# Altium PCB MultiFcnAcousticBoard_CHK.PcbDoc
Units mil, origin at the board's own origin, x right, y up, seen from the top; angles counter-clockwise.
Board outline 6000 x 4000 mil, 2 copper layers (Top Layer, Bottom Layer); 109 components, 99 nets, 325 pads, 43 vias.
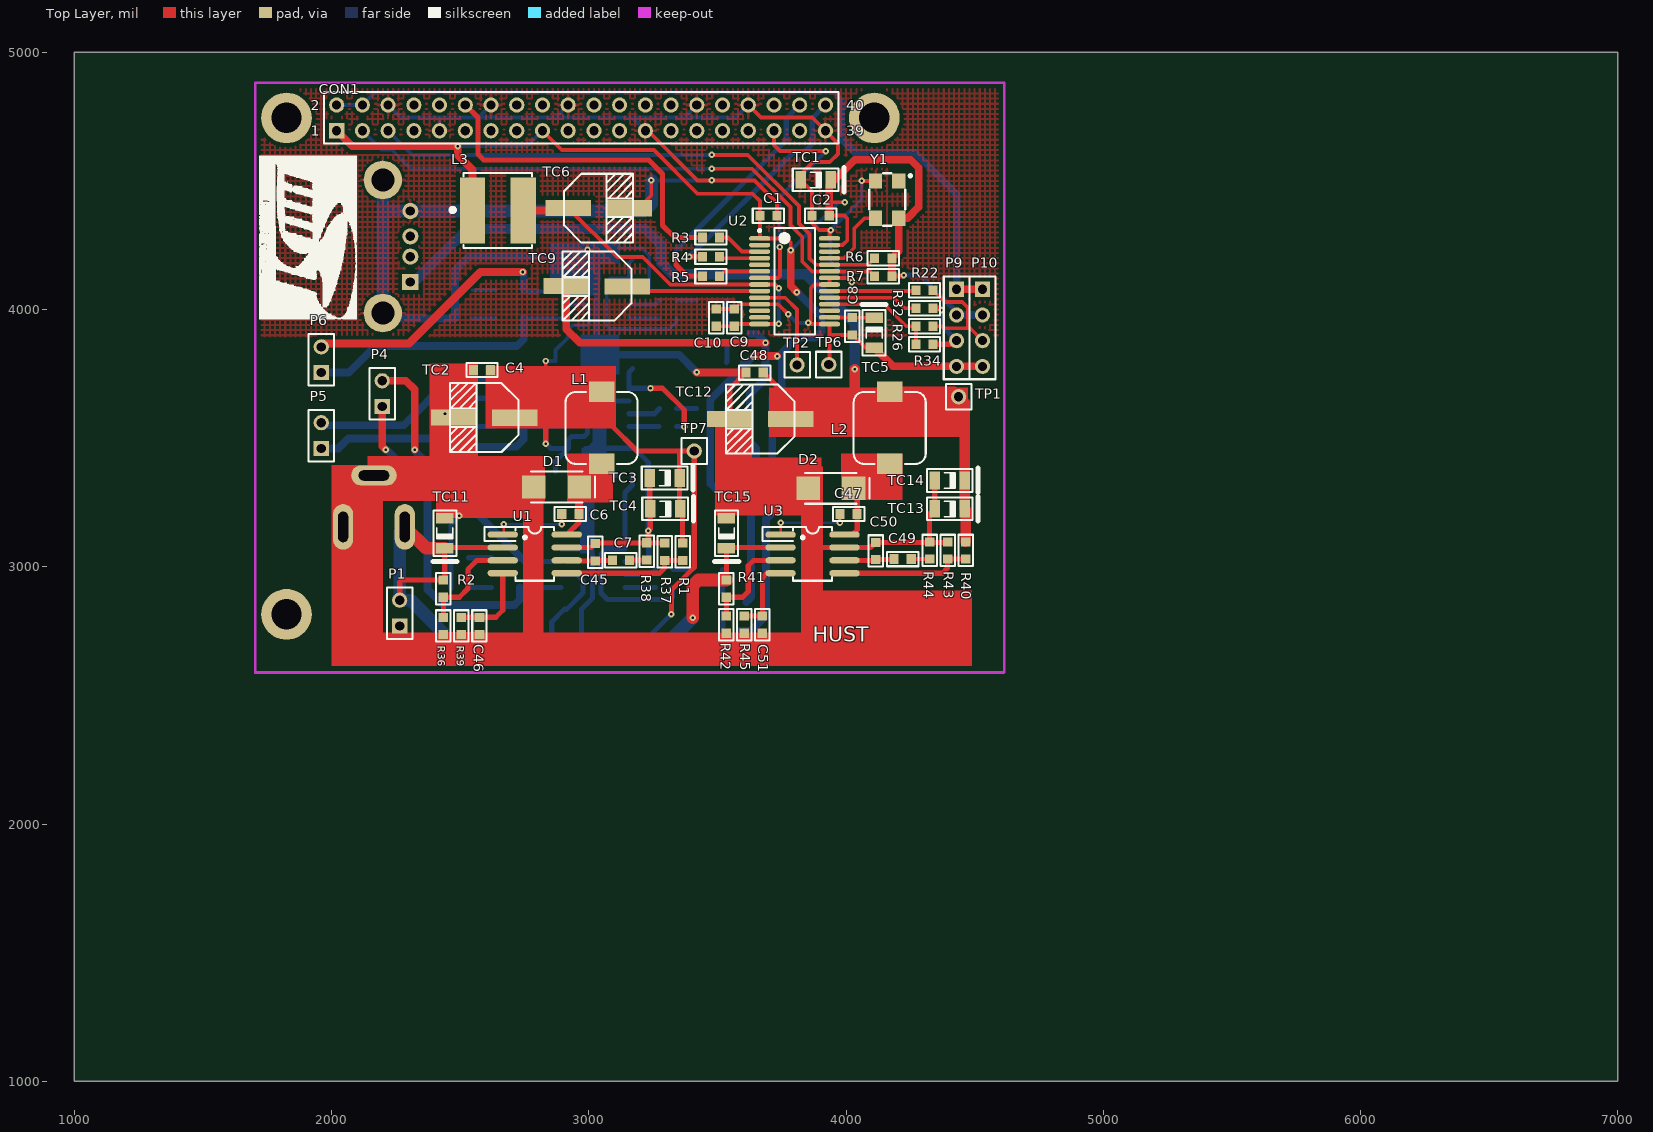
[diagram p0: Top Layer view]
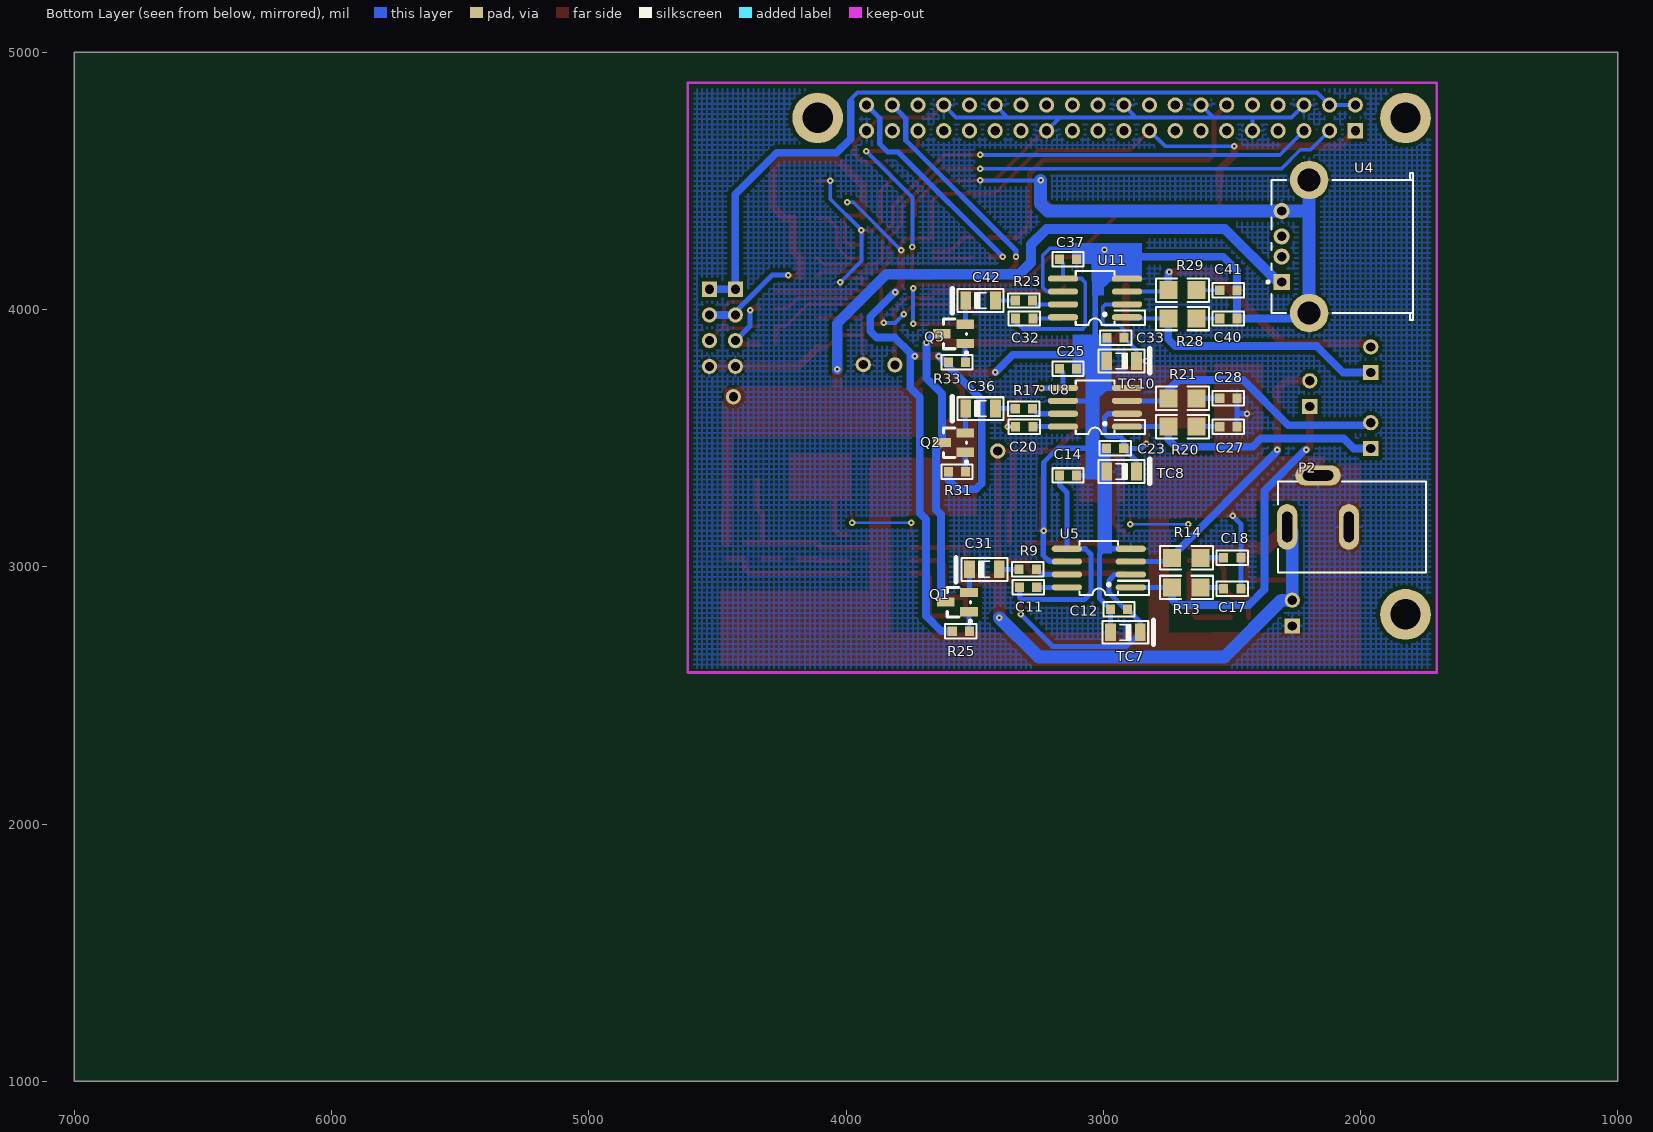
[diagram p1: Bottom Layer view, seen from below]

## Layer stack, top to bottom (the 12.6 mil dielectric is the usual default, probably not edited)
Top Solder: solder mask 0.4, Solder Resist, Dk 3.5
Top Layer: signal copper 1.4
Dielectric 1: dielectric 12.6, FR-4, Dk 4.8
Bottom Layer: signal copper 1.4
Bottom Solder: solder mask 0.4, Solder Resist, Dk 3.5

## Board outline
1000,1000 7000,1000 7000,5000 1000,5000

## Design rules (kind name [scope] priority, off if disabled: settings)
Clearance [All] p1: gap=15
PolygonConnect [All] p1: connectstyle=Relief reliefconductorwidth=10 reliefentries=4 polygonreliefangle="90 Angle" airgapwidth=10
RoutingVias [All] p1: holewidth=28 width=50 viastyle="Through Hole" minholewidth=5 minwidth=10 maxholewidth=50 maxwidth=100
SolderMaskExpansion [All] p1: expansion=4
Width [All] p1: maxlimit=100 minlimit=10 preferedwidth=30
30 further rules are at their usual default settings.

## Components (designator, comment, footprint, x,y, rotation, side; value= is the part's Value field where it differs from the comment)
C1 "0.1uF/0603" C0603 3698.46,4365 r180 top
C2 "0.1uF/0603" C0603 3901.54,4365 r0 top
C4 "0.1uF/0603" C0603 2585,3765 r0 top
C6 "0.1uF/0603" C0603 2928.46,3205 r0 top
C7 "180pF/0603" C0603 3125,3025 r180 top
C8 "0.1uF/0603" C0603 4025,3935 r90 top
C9 "0.1uF/0603" C0603 3565,3968.46 r270 top
C10 "0.1uF/0603" C0603 3495,3968.46 r270 top
C11 "10uF/0603" C0603 3292,2920 r180 bottom
C12 "0.1uF/0603" C0603 2938.54,2835 r180 bottom
C14 "10nF/0603" C0603 3137,3355 r0 bottom
C17 "0.1uF/0603" C0603 2498.54,2915 r0 bottom
C18 "0.1uF/0603" C0603 2498.54,3035 r0 bottom
C20 "10uF/0603" C0603 3307,3545 r180 bottom
C23 "0.1uF/0603" C0603 2953.54,3460 r180 bottom
C25 "10nF/0603" C0603 3137,3770 r0 bottom
C27 "0.1uF/0603" C0603 2513.54,3545 r0 bottom
C28 "0.1uF/0603" C0603 2513.54,3655 r0 bottom
C31 "1uF/1206" TAN_A 3462,2990 r0 bottom
C32 "10uF/0603" C0603 3307,3965 r180 bottom
C33 "0.1uF/0603" C0603 2952,3890 r180 bottom
C36 "1uF/1206" TAN_A 3477,3615 r0 bottom
C37 "10nF/0603" C0603 3137,4195 r0 bottom
C40 "0.1uF/0603" C0603 2513.54,3965 r0 bottom
C41 "0.1uF/0603" C0603 2513.54,4075 r0 bottom
C42 "1uF/1206" TAN_A 3477,4035 r0 bottom
C45 "10pF/0603" C0603 3025,3056.54 r270 top
C46 "0.015uF/0603" C0603 2575,2770 r90 top
C47 "0.1uF/0603" C0603 4010,3205 r0 top
C48 "0.1uF/0603" C0603 3645,3755 r0 top
C49 "180pF/0603" C0603 4220,3030 r180 top
C50 "10pF/0603" C0603 4115,3061.54 r270 top
C51 "0.015uF/0603" C0603 3675,2775 r90 top
CON1 "RPI_40PIN_CON" HDR2X20 2020,4695 r0 top
D1 "B320A-SMA" DIODE-SMA 2875,3310 r0 top
D2 "B320A-SMA" DIODE-SMA 3941.42,3305 r0 top
L1 "2.5uH/1264EY-100M=P3" L-SMD-7 3050,3540 r90 top
L2 "2.5uH/1264EY-100M=P3" L-SMD-7 4170,3540 r90 top
L3 "10uH/1264EY-100M=P3" INDUCTOR 2548.15,4385 r0 top
P1 "Header 2" HDR1X2 2265,2770 r90 top
P2 "Header 3" DC-005 2320,3155 r180 bottom
P4 "Header 2" HDR1X2 2197,3623 r90 top
P5 "Header 2" HDR1X2 1960,3460 r90 top
P6 "Header 2" HDR1X2 1960,3755 r90 top
P9 "Header 4" HDR1X4 4430,4079 r270 top
P10 "Header 4" HDR1X4 4531,4079 r270 top
Q1 "MMBT3904" SOT-23 3566.72,2862.5 r90 bottom
Q2 "MMBT3904" SOT-23 3581.72,3482.5 r90 bottom
Q3 "MMBT3904" SOT-23 3582,3905 r90 bottom
R1 "10.2K/0603" R0603 3365,3058.46 r90 top
R2 "150K/0603" R0603 2435,2915 r270 top
R3 "27 ohm/0603" R0603 3475,4280 r180 top
R4 "1K/0603" R0603 3475,4205 r180 top
R5 "27 ohm/0603" R0603 3475,4130 r180 top
R6 "1K/0603" R0603 4145,4200 r0 top
R7 "1K/0603" R0603 4145,4130 r0 top
R9 "10k" R0603 3293.54,2990 r180 bottom
R13 "4.7R" 0805 2622,2920 r0 bottom
R14 "4.7R" 0805 2622,3035 r0 bottom
R17 "10k" R0603 3308.54,3615 r180 bottom
R20 "4.7R" 0805 2637,3545 r0 bottom
R21 "4.7R" 0805 2637,3655 r0 bottom
R22 "0" R0603 4305,4075 r0 top
R23 "10k" R0603 3308.54,4035 r180 bottom
R25 "20k" R0603 3553.54,2750 r0 bottom
R26 "0" R0603 4305,3935 r0 top
R28 "4.7R" 0805 2637,3965 r0 bottom
R29 "4.7R" 0805 2637,4075 r0 bottom
R31 "20k" R0603 3568.54,3370 r0 bottom
R32 "0" R0603 4305,4005 r0 top
R33 "20k" R0603 3568.54,3795 r0 bottom
R34 "0" R0603 4305,3865 r0 top
R36 "48.7K/0603" R0603 2435,2770 r90 top
R37 "4.75K/0603" R0603 3295,3058.46 r270 top
R38 "75K/0603" R0603 3225,3060 r270 top
R39 "1M/0603" R0603 2505,2770 r90 top
R40 "10.2K/0603" R0603 4465,3063.46 r90 top
R41 "150K/0603" R0603 3535,2915 r270 top
R42 "48.7K/0603" R0603 3535,2775 r90 top
R43 "4.75K/0603" R0603 4395,3063.46 r270 top
R44 "75K/0603" R0603 4325,3063.46 r270 top
R45 "1M/0603" R0603 3605,2775 r90 top
TC1 "10uF/TAN/1206" TAN_A 3882,4504 r0 top
TC2 "1000uF" TAN_CAP 2712,3579 r180 top
TC3 "47uF" TAN_A 3295,3345 r0 top
TC4 "47uF" TAN_A 3296.93,3225 r0 top
TC5 "10uF/TAN/1206" TAN_A 4110,3910 r90 top
TC6 "10uF/TAN/1206" TAN_CAP 2920,4395 r0 top
TC7 "10uF" TAN_A 2913.93,2745 r180 bottom
TC8 "10uF" TAN_A 2928.93,3370 r180 bottom
TC9 "330uF" TAN_CAP 3150,4090 r180 top
TC10 "10uF" TAN_A 2928.93,3800 r180 bottom
TC11 "10uF" TAN_A 2440,3130 r270 top
TC12 "1000uF" TAN_CAP 3785,3574 r180 top
TC13 "47uF" TAN_A 4403.07,3225 r0 top
TC14 "47uF" TAN_A 4403.07,3335 r0 top
TC15 "10uF" TAN_A 3535,3130 r270 top
TP1 "VCC_5" TP 4440,3660 r0 top
TP2 "RPOUT" TP 3811.98,3784.16 r0 top
TP6 "GND" TP 3935,3785 r0 top
TP7 "VCC_12" TP 3411.98,3449.16 r0 top
U1 "TPS54432" SOIC-8 2790,3050 r0 top
U2 "WM8731SEDS/RV" SSOP-28 3800,4110 r0 top
U3 "TPS54432" SOIC-8 3870,3050 r0 top
U4 "USB" USB_A1 1795,4245 r180 bottom
U5 "TDA2822" SOIC-8 3017,2995 r0 bottom
U8 "TDA2822" SOIC-8 3032,3620 r0 bottom
U11 "TDA2822" SOIC-8 3032,4045 r0 bottom
Y1 "XATLS" 5032 4165,4430 r90 top

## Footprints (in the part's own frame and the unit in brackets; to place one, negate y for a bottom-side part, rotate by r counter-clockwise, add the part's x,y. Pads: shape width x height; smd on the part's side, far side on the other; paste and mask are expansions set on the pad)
0805 [mil]
  rect 70x70 smd: 1(0,0) 2(110,0)
  silkscreen extent -48,-45 158,46
5032 [mm]
  rect 1.5x1.3 smd: 1(1.778,-1.016) 2(1.778,1.27) 3(-1.905,1.27) 4(-1.905,-1.016)
  silkscreen extent -2.67,-2.29 2.54,1.91
C0603 [mm]
  rect 0.9x0.95 smd: 1(0.85,0) 2(-0.85,0)
  silkscreen extent -1.55,-0.71 1.55,0.71, body extent -0.85,-0.45 0.85,0.45, height 0.45
DC-005 [mm] "DC母座5.5mm"
  oval 2x4.5 hole 1 slot 3 at 90 deg: 1(0.889,0) 2(6.985,0)
  oval 4.5x2 hole 1 slot 3 at 0 deg: 3(3.937,5.08)
  silkscreen extent 0,-4.5 14.6,4.5, body extent 0,-4.45 14.6,4.44, height 11
DIODE-SMA [mm] "贴片二极管"
  rect 2.3x2.3 smd: 1(-2.25,0) 2(2.25,0)
  silkscreen extent -2.54,-1.52 3.81,1.52, body extent -2.92,-1.4 2.92,1.4, height 3
HDR1X2 [mm] "Connector; Header; 2 Position"
  rect 1.5x1.5 hole 0.9: 1(0,0)
  round 1.5 hole 0.9: 2(2.54,0)
  silkscreen extent -1.27,-1.27 3.81,1.27
HDR1X4 [mm] "Connector; Header; 4 Position"
  rect 1.5x1.5 hole 0.9: 1(0,0)
  round 1.5 hole 0.9: 2(2.54,0) 3(5.08,0) 4(7.62,0)
  silkscreen extent -1.27,-1.27 8.89,1.27
HDR2X20 [mm] "Connector; Header; 20x2 Position"
  rect 1.5x1.5 hole 0.9: 1(0,0)
  round 1.5 hole 0.9: 2(0,2.54) 3(2.54,0) 4(2.54,2.54) 5(5.08,0) 6(5.08,2.54) 7(7.62,0) 8(7.62,2.54) 9(10.16,0) 10(10.16,2.54) 11(12.7,0) 12(12.7,2.54) 13(15.24,0) 14(15.24,2.54) 15(17.78,0) 16(17.78,2.54) 17(20.32,0) 18(20.32,2.54) 19(22.86,0) 20(22.86,2.54) 21(25.4,0) 22(25.4,2.54) 23(27.94,0) 24(27.94,2.54) 25(30.48,0) 26(30.48,2.54) 27(33.02,0) 28(33.02,2.54) 29(35.56,0) 30(35.56,2.54) 31(38.1,0) 32(38.1,2.54) 33(40.64,0) 34(40.64,2.54) 35(43.18,0) 36(43.18,2.54) 37(45.72,0) 38(45.72,2.54) 39(48.26,0) 40(48.26,2.54)
  silkscreen extent -1.27,-1.27 49.53,3.81
INDUCTOR [mm]
  rect 2.5x6.5 smd: 1(0,0) 2(5,0)
  silkscreen extent -2.11,-3.7 5.88,3.7
L-SMD-7 [mm] "贴片电感7*7"
  rect 2x2.5 smd: 1(-3.556,0) 2(3.556,0)
  silkscreen extent -3.56,-3.56 3.56,3.56, body extent -3.56,-3.56 3.56,3.56, height 4
R0603 [mm]
  rect 0.9x0.95 smd: 1(0.85,0) 2(-0.85,0)
  silkscreen extent -1.55,-0.71 1.55,0.71, body extent -0.85,-0.45 0.85,0.45, height 0.45
SOIC-8 [mil] "SOIC, 8-Leads, Body 5.0x4.0mm (max), Pitch 1.27mm, IPC Medium Density"
  oval 118.11x24 smd: 1(-124.32,75) 2(-124.32,25) 3(-124.32,-25) 4(-124.32,-75) 5(124.32,-75) 6(124.32,-25) 7(124.32,25) 8(124.32,75)
  silkscreen extent -195,-104 75,104, body extent -75,-99 75,101, height 69
SOT-23 [mil]
  rect 36x68.9 smd: 1(-37.5,-45.28) 2(37.5,-45.28) 3(0.5,45.28)
  silkscreen extent -79,-55 58,40, body extent -58,-35 60,20, height 47
SSOP-28 [mm] "FT232"
  oval 2.1x0.45 smd: 1(-3.45,4.225) 2(-3.45,3.575) 3(-3.45,2.925) 4(-3.45,2.275) 5(-3.45,1.625) 6(-3.45,0.975) 7(-3.45,0.325) 8(-3.45,-0.325) 9(-3.45,-0.975) 10(-3.45,-1.625) 11(-3.45,-2.275) 12(-3.45,-2.925) 13(-3.45,-3.575) 14(-3.45,-4.225) 15(3.45,-4.225) 16(3.45,-3.575) 17(3.45,-2.925) 18(3.45,-2.275) 19(3.45,-1.625) 20(3.45,-0.975) 21(3.45,-0.325) 22(3.45,0.325) 23(3.45,0.975) 24(3.45,1.625) 25(3.45,2.275) 26(3.45,2.925) 27(3.45,3.575) 28(3.45,4.225)
  silkscreen extent -3.57,-5.25 2,5.25, body extent -2.8,-5.25 2.8,5.25, height 2
TAN_A [mm]
  rect 1.05x1.75 smd: 1(1.475,0) 2(-1.475,0)
  silkscreen extent -2.26,-1.17 2.79,1.22, body extent -1.6,-0.85 1.6,0.85, height 0.55
TAN_CAP [mm]
  rect 4.5x1.6 smd: 1(0,0) 2(6.02,-0.025)
  silkscreen extent -0.4,-3.43 6.4,3.37
TP [mm]
  round 1.5 hole 0.9: 1(-0.05,0.021)
  silkscreen extent -1.32,-1.25 1.22,1.29
USB_A1 [mm]
  rect 1.6x1.6 hole 0.92: 1(-12.99,-3.5)
  round 1.6 hole 0.92: 2(-12.99,-1) 3(-12.99,1) 4(-12.99,3.5)
  round 3.8 hole 2.3: 5(-10.28,6.57) 6(-10.28,-6.57)
  silkscreen extent -14.47,-7.25 0,7.25

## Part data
C1 C2 C4 C6 C7 C8 C9 C10 C11 C12 C14 C17 C18 C20 C23 C25 C27 C28 C31 C32 C33 C36 C37 C40 C41 C42 C45 C46 C47 C48 C49 C50 C51: library part C
D1 D2: library part "Diode 1N4003", "1 Amp General Purpose Rectifier"
L1 L2 L3: library part L
P1 P4 P5 P6: "Header, 2-Pin"
P2: "Header, 3-Pin"
P9 P10: "Header, 4-Pin"
Q1 Q2 Q3: "NPN Transistor"
R1 R2 R3 R4 R5 R6 R7 R9 R13 R14 R17 R20 R21 R22 R23 R25 R26 R28 R29 R31 R32 R33 R34 R36 R37 R38 R39 R40 R41 R42 R43 R44 R45: library part RES
TC1 TC2 TC3 TC4 TC5 TC6 TC7 TC8 TC9 TC10 TC11 TC12 TC13 TC14 TC15: library part TAN_C
TP1 TP2 TP6 TP7: library part Testpoint
U1 U3: library part TPS54332
U2: library part XWM8731EDS
Y1: "贴片有源晶振"

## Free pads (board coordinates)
  round 196.85 hole 118.11: 0(4110,4745) 1(1825,4745) 2(1825,2815)

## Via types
v1: diameter 25, hole 10, Top Layer to Bottom Layer, 43 vias

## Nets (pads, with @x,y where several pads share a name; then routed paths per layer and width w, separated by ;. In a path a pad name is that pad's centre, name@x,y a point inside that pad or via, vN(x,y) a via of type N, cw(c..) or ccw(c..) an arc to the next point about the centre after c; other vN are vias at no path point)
3V3: C1.1 C2.1 CON1.1 CON1.17 L3.1 P9.2 P10.2 R6.1 R7.1 R25.1 R31.1 R33.1 TC1.1 U2.1 U2.27 Y1.4 | length 7004.8
  Top Layer w15: L3.1 L3.1@2548.15,4492 ; CON1.17 2895,4620 3253,4620 3423,4450 3637,4450 3665,4422 C1.1 3665,4277.17 U2.1 3769.66,4276.34 3785,4261 v1(3785,4230) ; C2.1 3994,4365 4005,4354 4005,4269 3986.75,4250.75 U2.27 ; 3935,4415 3937,4417 v1(3995,4417)
  Top Layer w20: R7.1 4221,4130 v1(4225,4134)
  Top Layer w30: CON1.1 2080,4635 v1(2491,4635) 2491,4600 2548.15,4542.85 L3.1@2548.15,4492 ; v1(3639,3819) v1(3732,3819) ; v1(3785,4230) 3785,4092 v1(3809,4068) ; C2.1 3935,4415 3935,4483 4034,4582 4252,4582 4283,4551 4283,4399 4239,4355 Y1.4 4205,4226.54 R6.1 R7.1
  Bottom Layer w15: v1(2491,4635) 2760,4635 CON1.17 ; v1(3785,4230) 3972,4417 v1(3995,4417)
  Bottom Layer w20: v1(4225,4134) 4287,4134 4430,3991 P9.2
  Bottom Layer w30: R25.1 3630,2750 3689,2809 3689,3185 3713,3209 3713,3659 3750,3696 3750,3831 ; R31.1 3602,3339 3564,3301 3495,3301 3472,3324 3472,3649 3602,3779 R33.1 3615,3795 v1(3639,3819) ; v1(3732,3819) 3738,3819 3750,3831 ; v1(3809,4068) 3809,4069 3906,3972 3906,3916 3881,3891 3810,3891 3750,3831 ; P9.2 P10.2
3V_L: 
3V_R: 
5V: CON1.2 CON1.4 P9.1 P10.1 | length 3255
  Top Layer w30: P9.1 P10.1
  Bottom Layer w15: CON1.2 CON1.4 2169,4844 3955,4844 3982,4817 3982,4808
  Bottom Layer w30: 3982,4808 3982,4664 4037,4609 4269,4609 4430,4448 P9.1 P10.1
5V_L: 
5V_R: 
ACD_MISO: CON1.38 R5.1 | length 941.6
  Top Layer w20: v1(3339,4206) 3339,4173 3382,4130 R5.1
  Bottom Layer w20: v1(3339,4206) 3339,4229 3768,4658 3768,4743 CON1.38
ACD_MOSI: CON1.40 R4.1 | length 884.5
  Top Layer w20: v1(3390,4205) R4.1
  Bottom Layer w20: v1(3390,4205) 3797.5,4612.5 3837.5,4612.5 3869,4644 3869,4744 CON1.40
ACD_SCK: CON1.12 R3.1 | length 1335.2
  Top Layer w20: CON1.12 2569,4746 2569,4604 2592,4581 3233,4581 3287,4527 3287,4327 3334,4280 R3.1
ADCLRC: CON1.35 U2.7 | length 911
  Top Layer w15: U2.7 3735.8,4122.8 3743.8,4130.8 3743.8,4241.2 v1(3742,4243) ; CON1.35 3720,4639 3743,4616 v1(3922,4616)
  Bottom Layer w15: v1(3742,4243) 3742,4436 v1(3922,4616)
AMP1: C31.2 R9.2 | length 76.9
  Bottom Layer w20: R9.2 C31.2
AMP2: C36.2 R17.2 | length 76.9
  Bottom Layer w20: R17.2 C36.2
AMP3: C42.2 R23.2 | length 76.9
  Bottom Layer w15: R23.2 C42.2
BAT_IN: P1.2 P2.1 R2.2 R41.2 TC11.1 TC15.1 U1.2 U3.2 | length 2973.5
  Top Layer w20: P1.2 2265,2941 2272.46,2948.46 R2.2 2440,2953.46 TC11.1 2443.07,3075 U1.2 ; R41.2 TC15.1 3538.07,3075 U3.2
  Top Layer w50: P2.1 2368.07,3071.93 TC11.1 ; v1(3404,2802) 3404,2927 3425.46,2948.46 R41.2
  Bottom Layer w50: P2.1 2265,3135 P1.2 2308,2870 2529,2649 3251,2649 v1(3404,2802)
GND: C1.2 C2.2 C4.2 C8.2 C9.2 C10.2 C12.2 C14.2 C17.2 C18.2 C23.2 C25.2 C27.2 C28.2 C33.2 C37.2 C40.2 C41.2 C45.2 C46.2 C48.2 C50.2 C51.2 CON1.6 CON1.9 CON1.14 CON1.20 CON1.25 CON1.30 CON1.34 CON1.39 D1.1 D2.1 P1.1 P2.2 P2.3 P9.4 P10.4 R36.2 R37.2 R38.2 R39.2 R42.2 R43.2 R44.2 R45.2 TC1.2 TC2.2 TC3.2 TC4.2 TC5.2 TC6.2 TC7.2 TC8.2 TC10.2 TC11.2 TC12.2 TC13.2 TC14.2 TC15.2 TP6.1 U1.7 U2.11 U2.15 U2.21 U2.22 U2.28 U3.7 U4.4 U4.5 U4.6 U5.4 U5.6 U8.4 U8.6 U11.4 U11.6 Y1.2 | length 14433.1
  Top Layer w15: TC6.2 3193,4394 3243,4444 v1(3243,4503) ; CON1.25 3230,4695 3423,4502 v1(3478,4502) 3644,4502 3731.93,4414.07 C1.2 ; C10.2 C9.2 3583.5,4020.43 U2.11 3736.57,4020.43 v1(3776,3981) ; CON1.34 3669,4746 3869,4746 CON1.39 3969,4646 3969,4605 3937,4573 3871,4573 3823.93,4525.93 TC1.2 3868.07,4459.86 C2.2 3868.07,4336.93 3896,4309 v1(3940,4309) 3935.83,4304.83 U2.28 ; TP6.1 3935.83,3788.64 3935.83,3901.54 ; v1(4022,4106) 4005.2,4122.8 U2.22 U2.21 3877.2,4097.2 3863,4083 3863,3958 v1(3853,3948) 3857.34,3943.66 U2.15 3935.83,3901.54 ; v1(4061,4500) Y1.2 ; TC5.2 4074.61,3851.93 C8.2 3935.83,3901.54
  Top Layer w20: 2265,2699 P1.1 ; R36.2 R39.2 C46.2 ; U1.7 3010,3075 C45.2 3026.93,3091.93 R37.2 ; R38.2 3231,3099.46 v1(3231,3140) 3238.86,3147.86 TC4.2 3236.93,3226.93 TC3.2 ; TC12.2 3548,3691.46 C48.2 ; 3865,3085 3875,3085 3885,3075 U3.7 4095,3075 C50.2 4393.07,3095 R43.2 ; R44.2 4325,3205 TC13.2 TC14.2
  Top Layer w30: v1(3419,3756) 3420,3755 C48.2 ; TC5.2 4110.07,3851.93 4183,3779 P9.4 P10.4
  Bottom Layer w15: CON1.6 2268,4747 2426,4747 ; CON1.9 2420,4741 2426,4747 ; CON1.14 2572,4747 ; CON1.20 2872,4747 ; C37.2 3103.54,4238 3207,4238 3235,4210 3235,4086 3219,4070 U11.6 ; CON1.25 3168,4747 ; v1@3244,4502 v1(3478,4502) ; CON1.30 3372,4747 ; CON1.34 3572,4747 3372,4747 ; v1(3776,3981) 3809,3948 v1(3853,3948) ; v1(4022,4106) 3940,4188 v1(3940,4309) 4061,4430 v1(4061,4500) ; 2426,4747 2572,4747 ; 2572,4747 2872,4747 ; 2872,4747 3168,4747 ; 3168,4747 3372,4747
  Bottom Layer w20: v1(2441,3595) 2480.07,3595 ; C17.2 C18.2 2465.07,3166.07 v1(2497,3198) ; C27.2 2480.07,3595 ; C28.2 2480.07,3595 ; U5.4 2994,3070 3015,3049 3015,2878 C12.2 TC7.2 ; U8.4 2991,3695 3041,3645 ; TC8.2 C23.2 3002,3460 3041,3499 3041,3645 ; TC10.2 2985.46,3801.54 C33.2 3031,3890 3031,4065 2976,4120 U11.4 2982.68,4195 C37.2 ; v1(2995,4232) 3041,4232 ; 3035,3461 3176,3461 3231,3406 v1(3231,3140) 3233,3138 3233,3044 3209,3020 U5.6 ; 3038,3355 C14.2 ; U8.6 3041,3645
  Bottom Layer w30: U4.6 2221.06,3965 C40.2 C41.2 2480.07,4152.07 2533,4205 2909,4205 ; TC10.2 3017,3770 C25.2 ; 3092,3824 3351,3824 v1(3419,3756)
  Bottom Layer w50: U4.6 2199.72,4366 ; U4.5 2199.72,4366 ; v1@3244,4502 3244,4411 3215.8,4382.8 U4.4 2216.52,4382.8 2199.72,4366
I2C_SCL: CON1.5 R6.2 U2.24 | length 2213
  Top Layer w15: v1(3478,4601) 3618,4601 3817,4402 3817,4335 3858,4294 3858,4199 3883.02,4173.98 U2.24 4085.51,4173.98 R6.2
  Bottom Layer w15: CON1.5 2314,4601 v1(3478,4601)
I2C_SDA: CON1.3 R7.2 U2.23 | length 2322.2
  Top Layer w15: v1(3477.5,4547.5) 3634.5,4547.5 3784,4398 3784,4328 3830,4282 3830,4187 3868.61,4148.39 U2.23 4093.15,4148.39 R7.2
  Bottom Layer w15: CON1.3 2194,4621 2234,4621 2307.5,4547.5 v1(3477.5,4547.5)
L: 
LCHAL: 
LCHL: P10.3 R22.1 R26.1 | length 459.4
  Top Layer w15: R26.1 4373,3935 4381,3927 4474,3927 ; R22.1 4384.46,4029 4452,4029 4474,4007 4474,3927 ; P10.3 4483,3927 4474,3927
LLIN: R22.2 U2.20 | length 337.1
  Top Layer w15: U2.20 4268.15,4071.61 R22.2
LPOUT: TC9.1 U2.9 | length 521.8
  Top Layer w15: TC9.1 3168.39,4071.61 U2.9
MICBIAS1: 
MICBIAS2: 
MICIN: R26.2 R34.2 U2.18 | length 441.1
  Top Layer w15: U2.18 4148.57,4020.43 4234,3935 R26.2 R34.2
NetC6_1: C6.1 D1.2 L1.1 U1.8 | length 205.4
  Top Layer w20: U1.8 2961.93,3172.61 C6.1
  Top Layer w30: C6.1 2961.93,3308.35 D1.2
NetC6_2: C6.2 U1.1 | length 306.8
  Top Layer w10: U1.1 2670,3129.32 v1(2670,3165) ; v1(2895,3165) C6.2
  Bottom Layer w10: v1(2670,3165) v1(2895,3165)
NetC7_1: C7.1 C45.1 U1.6 | length 178.8
  Top Layer w20: U1.6 2916.24,3023.07 C45.1 3026.93,3025 C7.1
NetC7_2: C7.2 R38.1 | length 67.2
  Top Layer w20: C7.2 3160,3026.54 R38.1
NetC8_1: C8.1 TC5.1 U2.16 | length 174.7
  Top Layer w15: U2.16 4024.21,3969.25 C8.1 4025.39,3968.07 TC5.1
NetC9_1: C9.1 C10.1 L3.2 TC6.1 U2.8 U2.14 | length 1514.1
  Top Layer w15: TC6.1@2875,4385 2910,4385 TC6.1 3111,4204 3210,4204 3316.8,4097.2 U2.8 3724.8,4097.2 v1(3739,4083) ; C10.1 C9.1 3573.66,3943.66 U2.14 3664.51,3944 v1(3739,3944)
  Top Layer w30: L3.2 TC6.1@2875,4385
  Bottom Layer w15: v1(3739,3944) v1(3739,4083)
NetC11_1: C11.1 U5.8 | length 117.2
  Bottom Layer w20: U5.8 C11.1
NetC11_2: C11.2 C14.1 U5.5 | length 879.4
  Bottom Layer w20: C14.1 3170.46,3317.46 3141.32,3288.32 U5.5 3070,3070 3048,3048 3048,2898 3073,2873 3317,2873 3325.46,2881.46 C11.2
NetC17_1: C17.1 R13.1 | length 92.1
  Bottom Layer w20: C17.1 2537,2920 R13.1
NetC18_1: C18.1 R14.1 | length 90
  Bottom Layer w20: C18.1 R14.1
NetC20_1: C20.1 U8.8 | length 117.2
  Bottom Layer w20: U8.8 C20.1
NetC20_2: C20.2 C25.1 U8.5 | length 426.3
  Top Layer w20: v1(3240,3694) 3287,3694 3371,3610 v1(3371,3545)
  Bottom Layer w20: C25.1 3156.32,3755.85 U8.5 3157.32,3694 v1(3240,3694) ; C20.2 v1(3371,3545)
NetC21_1: 
NetC22_1: 
NetC24_1: 
NetC27_1: C27.1 R20.1 | length 90
  Bottom Layer w20: C27.1 R20.1
NetC28_1: C28.1 R21.1 | length 90
  Bottom Layer w20: C28.1 R21.1
NetC29_1: 
NetC30_2: 
NetC31_1: C31.1 Q1.2 | length 90.6
  Bottom Layer w20: C31.1 3520.07,2901.38 Q1.2
NetC32_1: C32.1 U11.8 | length 119.3
  Bottom Layer w15: U11.8 3161.32,3965 C32.1
NetC32_2: C32.2 C37.1 U11.5 | length 643.3
  Bottom Layer w15: C37.1 3156.32,4180.85 U11.5 3085,4120 3070,4105 3070,3935 3081,3924 3313,3924 3340.46,3951.46 C32.2
NetC34_1: 
NetC35_1: 
NetC36_1: C36.1 Q2.2 | length 95.6
  Bottom Layer w20: C36.1 3535.07,3521.38 Q2.2
NetC38_1: 
NetC40_1: C40.1 R28.1 | length 90
  Bottom Layer w15: C40.1 R28.1
NetC41_1: C41.1 R29.1 | length 90
  Bottom Layer w15: C41.1 R29.1
NetC42_1: C42.1 Q3.2 | length 93.2
  Bottom Layer w20: C42.1 3535.07,3944.15 Q3.2
NetC43_1: 
NetC44_2: 
NetC46_1: C46.1 R39.1 U1.4 | length 316.3
  Top Layer w20: R39.1 C46.1 2638.46,2803.46 2665.68,2830.68 U1.4
NetC47_1: C47.1 D2.2 L2.1 U3.8 | length 223.9
  Top Layer w20: U3.8 4025,3125 4043.46,3143.46 C47.1 4043.46,3291.54 D2.2
NetC47_2: C47.2 U3.1 | length 310.4
  Top Layer w10: U3.1 3745.68,3170.68 v1(3746.54,3171.54) ; v1(3976.54,3171.54) C47.2
  Bottom Layer w10: v1(3746.54,3171.54) v1(3976.54,3171.54)
NetC49_1: C49.1 C50.1 U3.6 | length 194.3
  Top Layer w10: C50.1@4111.93,3025 C50.1
  Top Layer w20: U3.6 C50.1@4111.93,3025 ; C50.1 4184.61,3028.07 C49.1
NetC49_2: C49.2 R44.1 | length 71.5
  Top Layer w15: C49.2 R44.1
NetC51_1: C51.1 R45.1 U3.4 | length 297.3
  Top Layer w20: R45.1 C51.1 3675,2958 3692,2975 U3.4
NetP11_1: 
NetP12_1: 
NetP12_2: 
NetQ1_1: Q1.1 R25.2 | length 75.6
  Bottom Layer w20: R25.2 3521.45,2751.38 Q1.1
NetQ1_3: Q1.3 Q2.3 Q3.3 TC9.2 | length 2095.1
  Top Layer w30: TC9.2 2913,3924 2966,3871 v1(3687,3871)
  Bottom Layer w30: Q1.3 3631,2882 3631,3203 3650,3222 3650,3460 Q2.3 3627,3673 3687,3733 v1(3687,3871) 3652.5,3905.5 Q3.3
NetQ2_1: Q2.1 R31.2 | length 75.6
  Bottom Layer w20: R31.2 3536.45,3371.38 Q2.1
NetQ3_1: Q3.1 R33.2 | length 73.2
  Bottom Layer w20: R33.2 3536.72,3796.65 Q3.1
NetR1_2: R1.2 R37.1 U1.5 | length 489
  Top Layer w20: U1.5 3275,2975 3295,2995 R37.1 R1.2
NetR2_1: R2.1 R36.1 U1.3 | length 412.1
  Top Layer w20: R36.1 R2.1 2496.54,2881.54 2530,2915 2530,2990 2565,3025 U1.3
NetR3_2: R3.2 U2.3 | length 178.4
  Top Layer w15: R3.2 3541,4280 3595.84,4225.16 U2.3
NetR4_2: R4.2 U2.4 | length 158
  Top Layer w15: R4.2 3513.9,4199.57 U2.4
NetR5_2: R5.2 U2.6 | length 163.3
  Top Layer w15: R5.2 3526.85,4148.39 U2.6
NetR9_1: R9.1 U5.7 | length 127
  Bottom Layer w20: U5.7 3240.07,2970 R9.1
NetR10_1: 
NetR12_1: 
NetR17_1: R17.1 U8.7 | length 127
  Bottom Layer w20: U8.7 3255.07,3595 R17.1
NetR18_1: 
NetR23_1: R23.1 U11.7 | length 125
  Bottom Layer w15: U11.7 3260.07,4020 R23.1
NetR27_1: 
NetR40_2: R40.2 R43.1 U3.5 | length 514
  Top Layer w20: U3.5 4375,2975 4395,2995 R43.1 R40.2
NetR41_1: R41.1 R42.1 U3.3 | length 401.8
  Top Layer w20: R42.1 R41.1 3597.54,2881.54 3620,2904 3620,3004 3641,3025 U3.3
NetU2_25: U2.25 Y1.3 | length 287.5
  Top Layer w15: U2.25 3991.57,4199.57 4032,4240 4032,4315 4072,4355 Y1.3
R: 
RCHAL: 
RCHL: P9.3 R32.1 R34.1 | length 267.5
  Top Layer w20: R34.1 4416,3865 P9.3 ; R32.1 v1@4366,4005
  Bottom Layer w20: v1(4373,3998) 4373,3936 P9.3
REF_L: 
REF_R: 
RLIN: R32.2 U2.19 | length 352.7
  Top Layer w15: U2.19 4185.98,4046.02 4227,4005 R32.2
RPOUT: TP2.1 U2.10 | length 379.9
  Top Layer w15: U2.10 3763.98,4046.02 3810,4000 TP2.1
SPL1_L: P4.1 R13.2 U5.1 | length 1387.3
  Top Layer w30: P4.1 2197,3469 v1(2211,3455)
  Bottom Layer w20: R13.2 U5.1
  Bottom Layer w30: v1(2211,3455) 2214,3455 2373,3296 2373,2912 2434,2851 2711,2851 2732,2872 R13.2
SPL1_R: P4.2 R14.2 U5.3 | length 1130.4
  Top Layer w30: P4.2 2289,3723 2323,3689 v1(2323,3455)
  Bottom Layer w20: R14.2 2747,3020 U5.3
  Bottom Layer w30: v1(2323,3455) 2323,3450 2732,3041 R14.2
SPL2_L: P5.1 R20.2 U8.1 | length 1038.1
  Bottom Layer w20: R20.2 U8.1
  Bottom Layer w30: P5.1 2027,3460 2066,3499 2387,3499 2419,3467 2718,3467 2747,3496 R20.2
SPL2_R: P5.2 R21.2 U8.3 | length 1076.4
  Bottom Layer w20: R21.2 2757,3645 U8.3
  Bottom Layer w30: P5.2 1970,3550 2280,3550 2456,3726 2707,3726 2747,3686 R21.2
SPL3_L: P6.1 R28.2 U11.1 | length 1083.6
  Bottom Layer w15: R28.2 2902.68,3965 U11.1
  Bottom Layer w30: P6.1 2067,3755 2170,3858 2720,3858 2747,3885 R28.2
SPL3_R: P6.2 R29.2 U11.3 | length 1139.5
  Top Layer w30: P6.2 1973,3868 2301,3868 2579,4146 v1(2744,4146)
  Bottom Layer w15: R29.2 2752,4070 U11.3
  Bottom Layer w30: v1(2744,4146) 2747,4143 R29.2
VCC_5V: C48.1 L2.2 R40.1 TC12.1 TC13.1 TC14.1 TP1.1 U4.1 | length 3869
  Top Layer w20: C48.1 3785,3648.46 TC12.1
  Top Layer w40: TC12.1 4129,3574 4170,3615 L2.2 4418.86,3680 TP1.1 4461.14,3637.72 TC14.1 TC13.1 4465,3221.14 R40.1 ; 4034,3626 v1(4034,3768)
  Bottom Layer w40: U4.1 2322.2,4107.2 2528,4313 3220,4313 3281,4252 3281,4182 3326,4137 3843,4137 4034,3946 v1(4034,3768)
VCC_12V: C4.1 C12.1 C23.1 C33.1 L1.2 R1.1 TC2.1 TC3.1 TC4.1 TC7.1 TC8.1 TC10.1 TP7.1 U5.2 U8.2 U11.2 | length 3333
  Top Layer w15: 2833,3742 v1(2833,3800)
  Top Layer w20: v1(2833,3479) 2833,3548 ; 3087,3550 3187,3450 3349,3450 ; v1(3321,2815) 3321,2909 3410,2998 TP7.1 3349,3450 ; R1.1 3365,3215 TC4.1 3353.07,3226.93 TC3.1 3353.07,3445.93 3349,3450
  Bottom Layer w15: v1(2833,3800) TC10.1 2870.86,3842.32 C33.1 2918.54,3920.54 2937,3939 2994,3939 3002,3947 3002,4010 2992,4020 U11.2
  Bottom Layer w20: v1(2833,3479) 2852,3460 C23.1 ; TC8.1 2870.86,3410.79 C23.1 ; U5.2 2955,2970 2978,2947 2978,2899 2914,2835 C12.1 2855.86,2785.79 TC7.1 2910.86,2690 3196,2690 v1(3321,2815) ; U8.2 2981,3595 2995,3581 2995,3519 2982,3506 2934,3506 2920.07,3492.07 C23.1
pads on no net: CON1.7 CON1.8 CON1.10 CON1.11 CON1.13 CON1.15 CON1.16 CON1.18 CON1.19 CON1.21 CON1.22 CON1.23 CON1.24 CON1.26 CON1.27 CON1.28 CON1.29 CON1.31 CON1.32 CON1.33 CON1.36 CON1.37 U2.2 U2.5 U2.12 U2.13 U2.17 U2.26 U4.2 U4.3 Y1.1

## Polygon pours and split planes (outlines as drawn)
GND on Top Layer "Keep-Out Layer-No Net" (hatched 90Degree grid 20 track 8, remove dead copper, pour order 6): 1702,3895 4616,3895 4615,3896 4615,4319 4615,4882 4495,4882 1704,4882
GND on Bottom Layer "Keep-Out Layer-No Net" (hatched 90Degree grid 20 track 8, remove dead copper, pour order 8): 1704,4882 4615,4882 4615,2585 4613,2583 4588,2583 1707,2583

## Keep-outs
Keep-Out Layer:
  lines w10: 1704,2589 1704,4882 1718,4882 4615,4882 4615,2603 4615,2590 4614,2589 1707,2589

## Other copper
Top Layer:
  rectangle net GND: 3852,2652 4489,2907
  rectangle net GND: 2407,3189 2795,3270
  rectangle net VCC_5V: 3700,3504 4474,3696
  rectangle net VCC_12V: 2599,3537 3106,3780
  rectangle net GND: 2000,2615 4490,2745
  rectangle net GND: 2000,2630 2200,3395
  rectangle net GND: 2745,2680 2825,3390
  rectangle net GND: 3825,2680 3910,3390
  rectangle net GND: 2140,3255 2830,3430
  rectangle net GND: 2380,3355 2570,3790
  rectangle net GND: 3490,3260 3905,3425
  rectangle net GND: 3490,3200 3880,3295
  rectangle net GND: 3490,3360 3635,3575
  rectangle net NetC47_1: 3980,3260 4220,3440
  rectangle net NetC6_1: 2915,3250 3095,3440
Bottom Layer:
  rectangle net GND: 2966,3052 3023,3356
  rectangle net GND: 2997,4054 3043,4185
  rectangle net GND: 2849,4177 3122,4259
  rectangle net GND: 2849,4108 3046,4220
  rectangle net GND: 2968,3684 3066,3748
  rectangle net GND: 2968,3748 3120,3903
  rectangle net GND: 2972,3339 3069,3461
  rectangle net GND: 3015,3339 3069,3778

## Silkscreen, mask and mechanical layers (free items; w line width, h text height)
Top Overlay:
  drawing of 4822 lines, arcs and shapes, not listed
  text "HUST" at 3870,2690 h100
